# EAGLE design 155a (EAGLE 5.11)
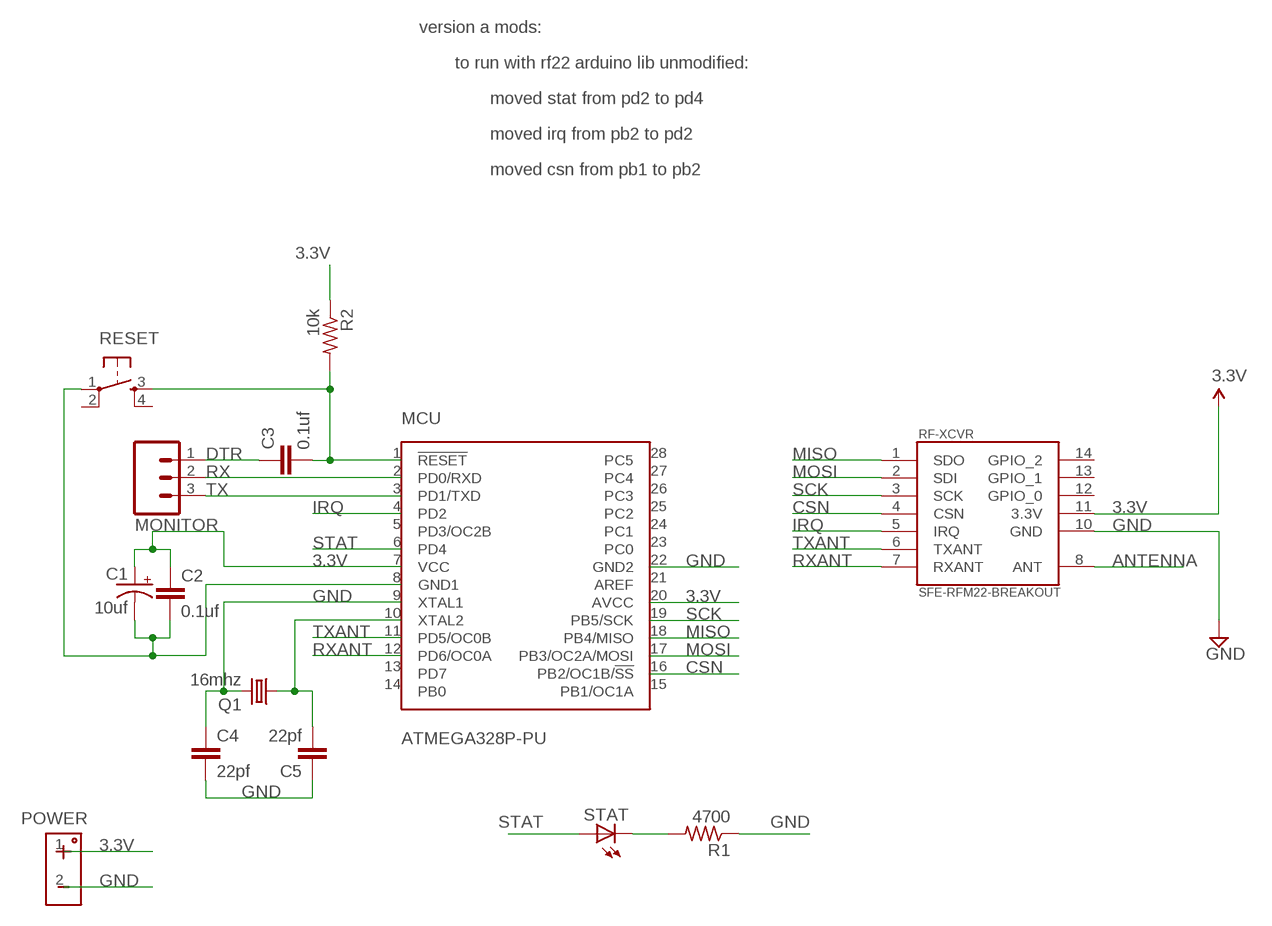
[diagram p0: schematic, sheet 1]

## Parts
C1  10uf  CPOL-USE2-5  [E2-5]
C2  0.1uf  C-EU050-024X044  [C050-024X044]
C3  0.1uf  C-EU050-024X044  [C050-024X044]
C4  22pf  C-EU050-024X044  [C050-024X044]
C5  22pf  C-EU050-024X044  [C050-024X044]
MCU  ATMEGA328P-PU  [DIL28-3]
MONITOR  M03PTH  [1X03]
POWER  HEADER-POWER  [HEADER-POWER]
Q1  16mhz  CRYSTALHC49U-V  [HC49U-V]
R1  4700  R-US_0309/10  [0309/10]
R2  10k  R-US_0207/2V  [0207/2V]
RESET  TAC_SWITCHPTH  [TACTILE-PTH]
RF-XCVR  SFE-RFM22-BREAKOUT  [SFE-RFM22-BREAKOUT]
STAT  LED5MM  [LED5MM]

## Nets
3.3V: C1.+ C2.1 MCU.7(VCC) MCU.20(AVCC) POWER.1 R2.1 RF-XCVR.11(3.3V)
ANTENNA: RF-XCVR.8(ANT)
CSN: MCU.16(PB2/OC1B/!SS) RF-XCVR.4(CSN)
DTR: C3.1 MONITOR.1
GND: C1.- C2.2 C4.2 C5.1 MCU.8(GND1) MCU.22(GND2) POWER.2 R1.1 RESET.1 RF-XCVR.10(GND)
IRQ: MCU.4(PD2) RF-XCVR.5(IRQ)
MISO: MCU.18(PB4/MISO) RF-XCVR.1(SDO)
MOSI: MCU.17(PB3/OC2A/MOSI) RF-XCVR.2(SDI)
N$1: C3.2 MCU.1(!RESET) R2.2 RESET.3
N$2: R1.2 STAT.K(C)
N$4: C5.2 MCU.10(XTAL2) Q1.1
N$5: C4.1 MCU.9(XTAL1) Q1.2
RX: MCU.2(PD0/RXD) MONITOR.2
RXANT: MCU.12(PD6/OC0A) RF-XCVR.7(RXANT)
SCK: MCU.19(PB5/SCK) RF-XCVR.3(SCK)
STAT: MCU.6(PD4) STAT.A
TX: MCU.3(PD1/TXD) MONITOR.3
TXANT: MCU.11(PD5/OC0B) RF-XCVR.6(TXANT)
Unconnected: MCU.5(PD3/OC2B) MCU.13(PD7) MCU.14(PB0) MCU.15(PB1/OC1A) MCU.21(AREF) MCU.23(PC0) MCU.24(PC1) MCU.25(PC2) MCU.26(PC3) MCU.27(PC4) MCU.28(PC5) RESET.2 RESET.4 RF-XCVR.12(GPIO_0) RF-XCVR.13(GPIO_1) RF-XCVR.14(GPIO_2)

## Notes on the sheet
- version a mods:
- to run with rf22 arduino lib unmodified:
- moved stat from pd2 to pd4
- moved irq from pb2 to pd2
- moved csn from pb1 to pb2

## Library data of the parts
C1 = rcl:CPOL-US: POLARIZED CAPACITOR, American symbol
C2-C5 = rcl:C-EU: CAPACITOR, European symbol
MCU = trl:ATMEGA328P-PU
MONITOR = SparkFun:M03: Header 3 Standard 3-pin 0.1" header. Use with straight break away headers (SKU : PRT-00116), right angle break away headers (PRT-00553), swiss pins (PRT-00743), machine pins (PRT-00117), and female headers (PRT-00115). Molex polarized connector foot print use with SKU : PRT-08232 with associated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
POWER = trl:HEADER-POWER
Q1 = crystal:CRYSTAL: CRYSTAL; OC_FARNELL: 1666969; OC_NEWARK: unknown
R1 R2 = resistor:R-US_: RESISTOR, American symbol
RESET = SparkFun2011-02-20:TAC_SWITCH: Momentary Switch Button commonly used for reset or general input. Spark Fun Electronics SKU : COM-00097
RF-XCVR = trl:SFE-RFM22-BREAKOUT
STAT = led:LED: LED

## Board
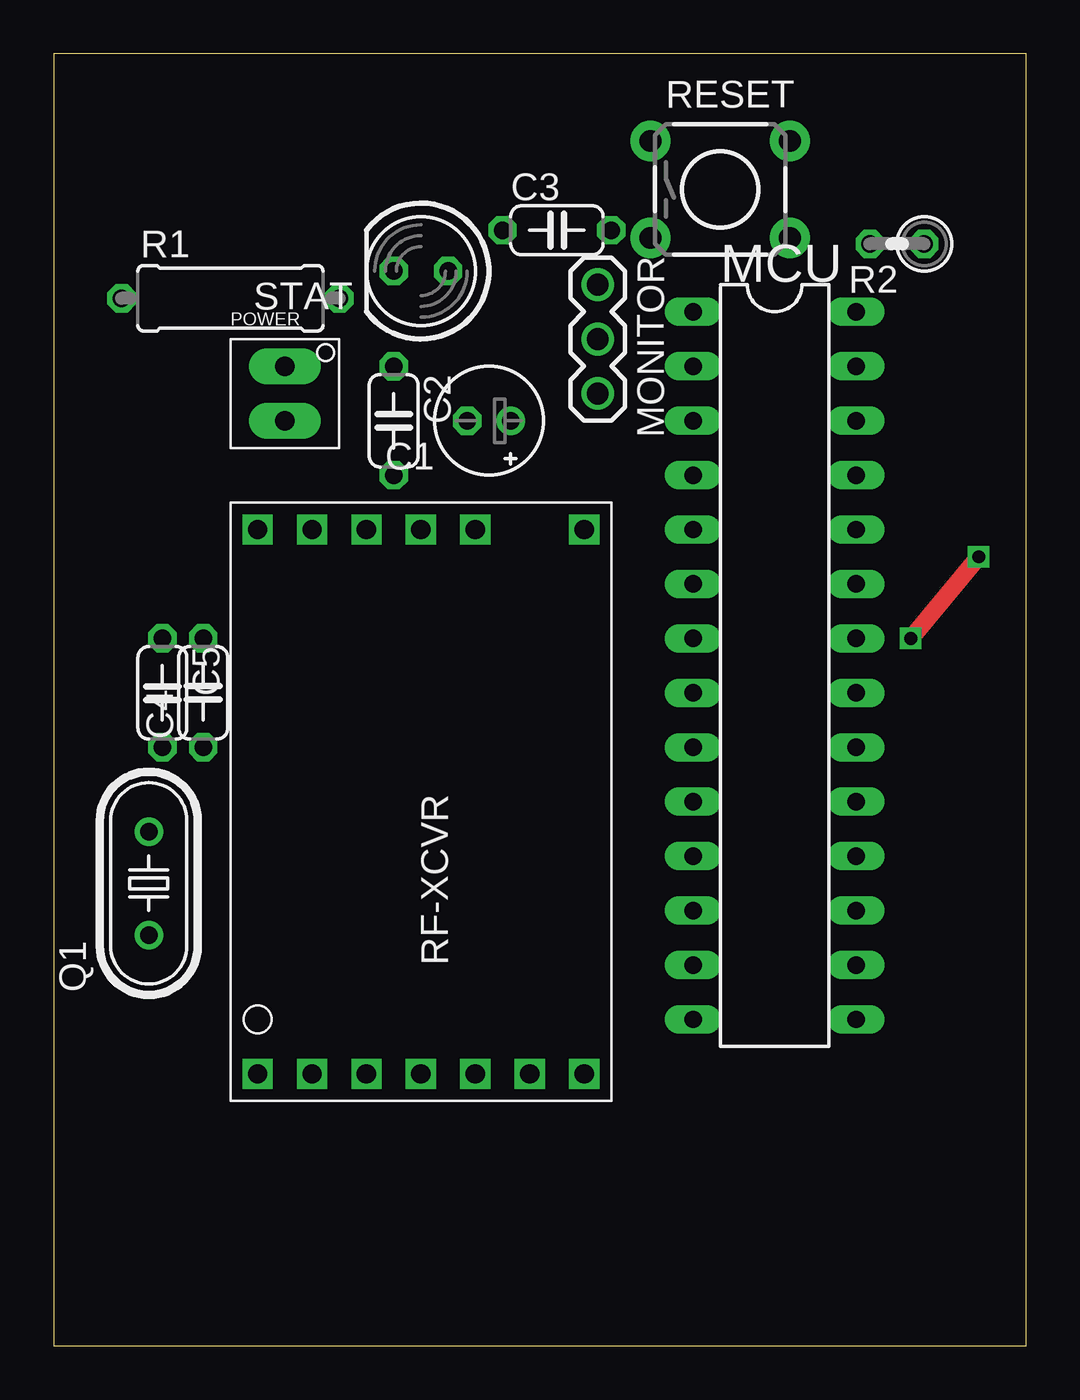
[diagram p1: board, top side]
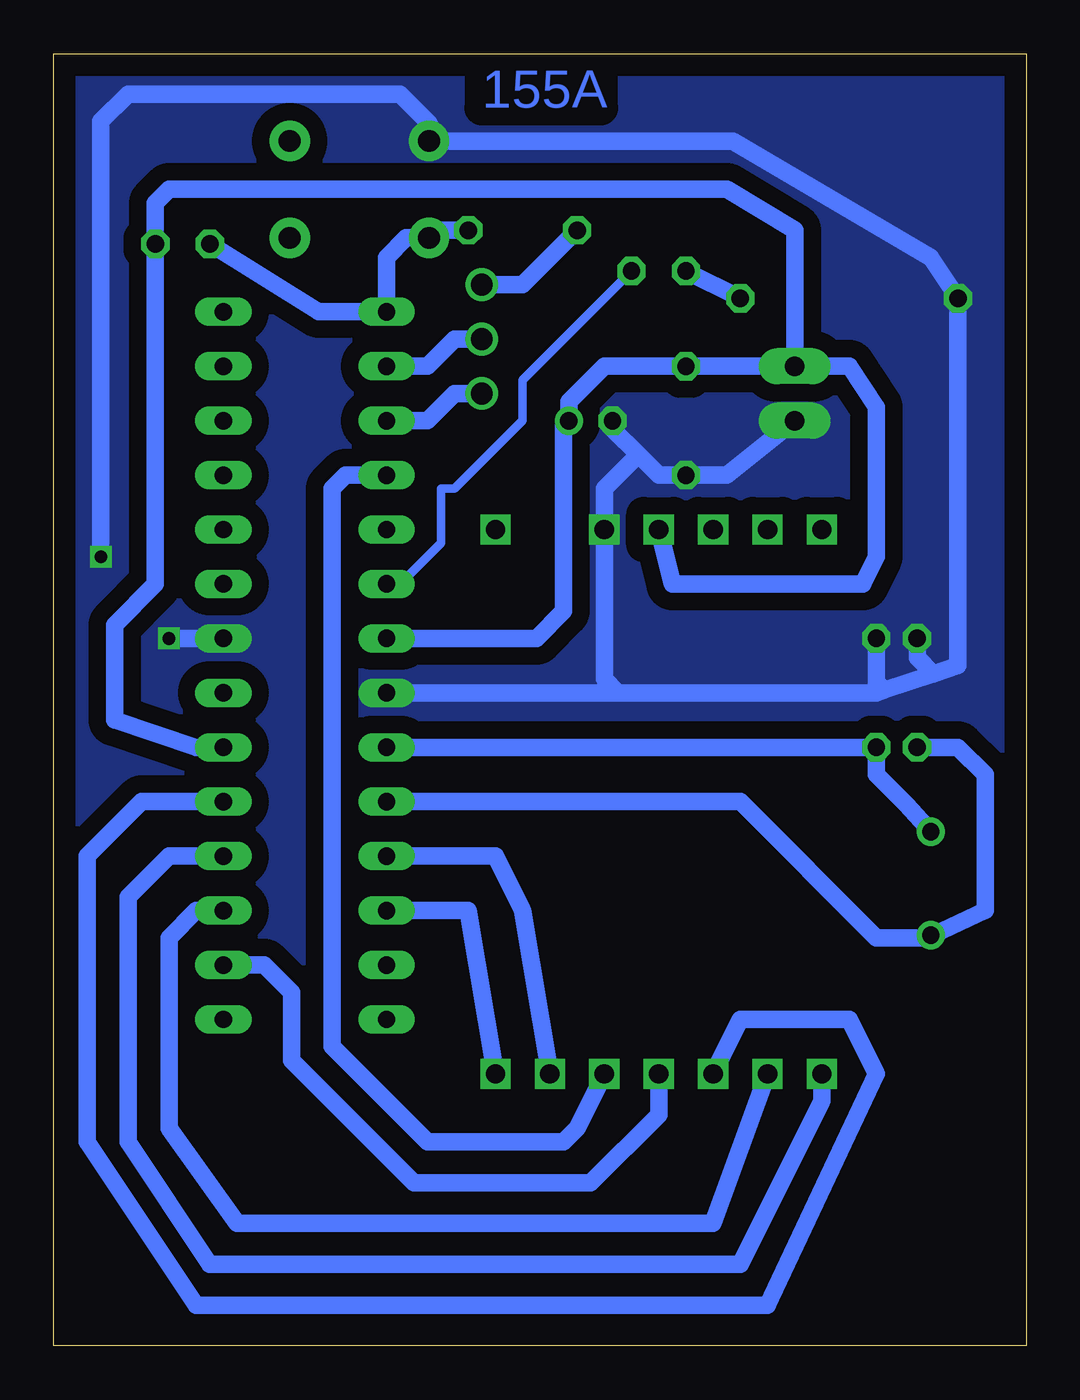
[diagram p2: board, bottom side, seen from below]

Size 45.39 x 60.31 mm. Coordinates in mm from the lower left corner, seen from the top.
Outline: 0,0 45.39,0 45.39,60.31 0,60.31 0,0
Copper layers (1*16): Top 0.035mm / dielectric 1.5mm / Bottom 0.035mm
Design rules "default": minimum track width 10mil, minimum drill 0.6mm, track to track 8mil, track to pad 8mil, pad to pad 8mil, via to via 8mil, smd to smd 8mil, copper to edge 40mil, drill to drill 8mil, minimum pad ring 10mil, minimum via ring 8mil, stop-mask expansion 4mil, vias tented up to drill 0mil, thermal gap 10mil

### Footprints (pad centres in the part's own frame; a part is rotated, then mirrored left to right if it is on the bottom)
E2-5 = drill 0.813 pad 1.27 round: + -1.016,0 | drill 0.813 pad 1.27 octagon: - 1.016,0
C050-024X044 = drill 0.813 octagon: 1 -2.54,0; 2 2.54,0
DIL28-3 = drill 0.813 long: 1 -16.51,-3.81; 2 -13.97,-3.81; 3 -11.43,-3.81; 4 -8.89,-3.81; 5 -6.35,-3.81; 6 -3.81,-3.81; 7 -1.27,-3.81; 8 1.27,-3.81; 9 3.81,-3.81; 10 6.35,-3.81; 11 8.89,-3.81; 12 11.43,-3.81; 13 13.97,-3.81; 14 16.51,-3.81; 15 16.51,3.81; 16 13.97,3.81; 17 11.43,3.81; 18 8.89,3.81; 19 6.35,3.81; 20 3.81,3.81; 21 1.27,3.81; 22 -1.27,3.81; 23 -3.81,3.81; 24 -6.35,3.81; 25 -8.89,3.81; 26 -11.43,3.81; 27 -13.97,3.81; 28 -16.51,3.81
1X03 = drill 1.016 round: 1 0,0; 2 2.54,0; 3 5.08,0
HEADER-POWER = drill 0.9 pad 1.676 long: 1 0,1.27; 2 0,-1.27
HC49U-V = drill 0.813 round: 1 -2.413,0; 2 2.413,0
0309/10 = drill 0.813 octagon: 1 -5.08,0; 2 5.08,0
0207/2V = drill 0.813 octagon: 1 -1.27,0; 2 1.27,0
TACTILE-PTH = drill 1.016 pad 1.88 round: 1 -3.251,2.261; 2 3.251,2.261; 3 -3.251,-2.261; 4 3.251,-2.261
SFE-RFM22-BREAKOUT = drill 0.9 square: 1 -12.7,7.62; 2 -12.7,5.08; 3 -12.7,2.54; 4 -12.7,0; 5 -12.7,-2.54; 6 -12.7,-5.08; 7 -12.7,-7.62; 8 12.7,-7.62; 10 12.7,-2.54; 11 12.7,0; 12 12.7,2.54; 13 12.7,5.08; 14 12.7,7.62
LED5MM = drill 0.813 octagon: A -1.27,0; K 1.27,0

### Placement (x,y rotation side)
C1  20.32,43.18 180 top
C2  15.88,43.18 270 top
C3  23.5,52.07 0 top
C4  6.99,30.48 90 top
C5  5.08,30.48 270 top
MCU  33.66,31.75 270 top
MONITOR  25.4,49.53 270 top
POWER  10.79,44.45 0 top
Q1  4.45,21.59 90 top
R1  8.26,48.9 0 top
R2  39.37,51.44 180 top
RESET  31.11,53.98 0 top
RF-XCVR  17.14,25.4 90 top
STAT  17.14,50.16 180 top

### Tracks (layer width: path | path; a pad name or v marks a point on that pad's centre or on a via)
3.3V
  Bottom 0.813: POWER.1 C2.1 19.68,45.72 21.34,44.07 C1.+ 21.59,42.93 21.59,34.29 22.86,33.02 MCU.7 | RF-XCVR.11 16.51,35.56 7.62,35.56 6.99,36.83 6.99,43.81 8.26,45.72 POWER.1 | POWER.1 10.79,52.07 13.97,53.98 40.01,53.98 40.64,53.34 R2.1 40.64,35.56 42.55,33.66 42.55,29.21 38.73,27.94 MCU.20
CSN
  Bottom 0.813: MCU.16 35.56,17.78 34.29,16.51 34.29,13.34 28.57,7.62 20.32,7.62 17.14,10.79 RF-XCVR.4
DTR
  Bottom 0.813: MONITOR.1 23.5,49.53 C3.1
GND  (via drill 0.6)
  Top 0.813: v43.18,36.83 v40.01,33.02
  Bottom 0.813: POWER.2 13.97,40.64 C2.2 17.14,40.64 18.1,41.59 | 4.32,31.37 3.17,31.75 R1.1 4.45,50.8 13.69,56.24 RESET.1 27.86,57.07 29.21,58.42 41.91,58.42 43.18,57.15 v43.18,36.83 | 4.32,31.37 6.6,30.61 | 6.6,30.61 6.99,30.48 19.05,30.48 | C1.- 19.3,42.8 18.1,41.59 | C4.2 6.99,30.99 6.6,30.61 | C5.1 5.08,32.13 4.32,31.37 | v40.01,33.02 MCU.22 | 19.05,30.48 19.68,31.11 RF-XCVR.10 19.68,40.01 18.1,41.59 | 19.05,30.48 MCU.8
  pour Bottom (isolate 0.813, no thermals): 0,59.69 45.72,59.69 45.72,0 0,0
IRQ
  Bottom 0.813: RF-XCVR.5 20.95,10.16 21.59,9.53 27.94,9.53 32.38,13.97 32.38,40.01 31.75,40.64 MCU.4
MISO
  Bottom 0.813: RF-XCVR.1 9.53,11.43 13.34,3.81 38.1,3.81 41.91,9.53 41.91,20.95 40.01,22.86 MCU.18
MOSI
  Bottom 0.813: MCU.17 38.73,20.32 40.01,19.05 40.01,10.16 36.83,5.71 14.61,5.71 RF-XCVR.2
N$1
  Bottom 0.813: R2.2 33.02,48.26 MCU.1 29.84,50.8 28.93,51.71 RESET.3 27.51,52.07 C3.2
N$2
  Bottom 0.813: R1.2 STAT.K
N$4
  Bottom 0.813: MCU.10 13.34,25.4 6.99,19.05 4.57,19.05 Q1.1 4.32,19.18 1.91,20.32 1.91,26.67 3.17,27.94 C5.2
N$5
  Bottom 0.813: MCU.9 C4.1 6.99,26.67 5.59,25.27 Q1.2
RX
  Bottom 0.813: MONITOR.2 26.67,46.99 27.94,45.72 MCU.2
RXANT
  Bottom 0.813: MCU.12 26.04,20.32 RF-XCVR.7
SCK
  Bottom 0.813: RF-XCVR.3 13.34,15.24 8.26,15.24 6.99,12.7 12.06,1.91 38.73,1.91 43.81,9.53 43.81,22.86 41.27,25.4 MCU.19
STAT
  Bottom 0.406: MCU.6 29.21,35.56 27.3,37.47 27.3,40.01 26.67,40.01 23.5,43.18 23.5,45.09 STAT.A
TX
  Bottom 0.813: MCU.3 27.94,43.18 26.67,44.45 MONITOR.3
TXANT
  Bottom 0.813: RF-XCVR.6 23.5,20.32 24.77,22.86 MCU.11

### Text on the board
Bottom: 155A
